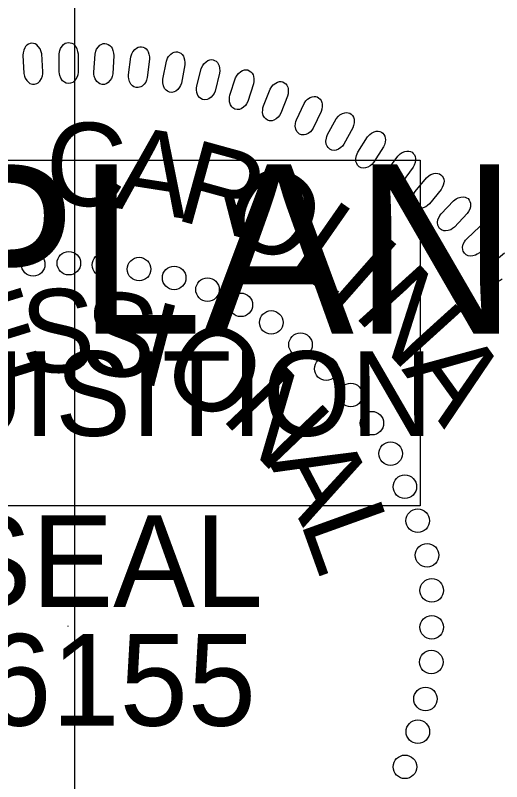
# Model space of a CAD drawing. Extents: x 497599 to 513368, y 404140 to 476034.
# Drawn here: x 507304.6 to 507337.7, y 439736.2 to 439788.3 of the extents above; entities that cross this region are included whole.
import ezdxf

# ---------------------------------------------------------------- set-up
doc = ezdxf.new("R2010")
doc.units = 0
for name, color, linetype in [('Sheet Layout Profile Border Port 2', 7, 'Continuous'), ('Sheet PE Seal Cell', 7, 'Continuous'), ('Sheet Sticker Incomplete CELL', 7, 'Continuous')]:
    doc.layers.add(name, color=color, linetype=linetype)

msp = doc.modelspace()

# ---------------------------------------------------------------- linework, layer by layer
at = {"layer": 'Sheet Layout Profile Border Port 2'}
msp.add_lwpolyline([(505908.678, 439836.144), (507308.678, 439836.144), (507308.678, 439336.144), (505908.678, 439336.144)], close=True, dxfattribs=at)
at = {"layer": 'Sheet PE Seal Cell'}
msp.add_line((507308.224, 439746.764), (507308.224, 439746.717), dxfattribs=at)
for points in [[(507306.517, 439784.44), (507306.441, 439785.665), (507306.39, 439785.881), (507306.329, 439786.017), (507306.206, 439786.18), (507306.103, 439786.283), (507305.986, 439786.356), (507305.879, 439786.389), (507305.765, 439786.401), (507305.655, 439786.374), (507305.538, 439786.337), (507305.436, 439786.271), (507305.338, 439786.165), (507305.284, 439786.082), (507305.226, 439785.928), (507305.177, 439785.745), (507305.165, 439785.585), (507305.236, 439784.33), (507305.269, 439784.162), (507305.323, 439784.026), (507305.422, 439783.872), (507305.543, 439783.74), (507305.644, 439783.666), (507305.805, 439783.616), (507305.956, 439783.605), (507306.102, 439783.655), (507306.204, 439783.711), (507306.324, 439783.819), (507306.433, 439783.995), (507306.489, 439784.179), (507306.511, 439784.31)], [(507307.633, 439784.449), (507307.633, 439785.676), (507307.671, 439785.895), (507307.723, 439786.035), (507307.835, 439786.204), (507307.933, 439786.314), (507308.045, 439786.394), (507308.149, 439786.434), (507308.262, 439786.454), (507308.373, 439786.434), (507308.493, 439786.404), (507308.597, 439786.344), (507308.702, 439786.244), (507308.762, 439786.164), (507308.829, 439786.014), (507308.889, 439785.835), (507308.912, 439785.675), (507308.918, 439784.419), (507308.896, 439784.249), (507308.851, 439784.11), (507308.761, 439783.95), (507308.649, 439783.81), (507308.552, 439783.731), (507308.395, 439783.671), (507308.246, 439783.651), (507308.096, 439783.691), (507307.992, 439783.741), (507307.864, 439783.84), (507307.745, 439784.011), (507307.677, 439784.19), (507307.648, 439784.32)], [(507309.992, 439784.423), (507310.069, 439785.647), (507310.12, 439785.864), (507310.181, 439786), (507310.304, 439786.162), (507310.408, 439786.265), (507310.525, 439786.338), (507310.632, 439786.371), (507310.745, 439786.384), (507310.856, 439786.356), (507310.973, 439786.319), (507311.074, 439786.253), (507311.172, 439786.147), (507311.226, 439786.063), (507311.285, 439785.91), (507311.333, 439785.727), (507311.345, 439785.567), (507311.273, 439784.312), (507311.24, 439784.144), (507311.186, 439784.007), (507311.087, 439783.854), (507310.966, 439783.722), (507310.864, 439783.648), (507310.704, 439783.598), (507310.553, 439783.587), (507310.406, 439783.637), (507310.305, 439783.694), (507310.185, 439783.801), (507310.076, 439783.978), (507310.02, 439784.161), (507309.999, 439784.293)], [(507312.354, 439784.248), (507312.509, 439785.464), (507312.573, 439785.678), (507312.643, 439785.809), (507312.775, 439785.963), (507312.886, 439786.06), (507313.007, 439786.125), (507313.115, 439786.152), (507313.229, 439786.157), (507313.338, 439786.123), (507313.452, 439786.079), (507313.549, 439786.006), (507313.64, 439785.894), (507313.69, 439785.808), (507313.738, 439785.65), (507313.774, 439785.465), (507313.776, 439785.304), (507313.626, 439784.056), (507313.582, 439783.891), (507313.521, 439783.758), (507313.411, 439783.611), (507313.283, 439783.487), (507313.177, 439783.42), (507313.013, 439783.38), (507312.862, 439783.379), (507312.719, 439783.437), (507312.621, 439783.5), (507312.507, 439783.615), (507312.41, 439783.798), (507312.366, 439783.985), (507312.353, 439784.117)], [(507314.694, 439783.961), (507314.924, 439785.166), (507315.002, 439785.374), (507315.079, 439785.501), (507315.222, 439785.647), (507315.337, 439785.736), (507315.462, 439785.794), (507315.573, 439785.813), (507315.687, 439785.812), (507315.793, 439785.772), (507315.905, 439785.72), (507315.996, 439785.641), (507316.081, 439785.523), (507316.124, 439785.434), (507316.162, 439785.274), (507316.188, 439785.087), (507316.18, 439784.926), (507315.951, 439783.69), (507315.897, 439783.528), (507315.827, 439783.399), (507315.709, 439783.259), (507315.572, 439783.143), (507315.462, 439783.083), (507315.297, 439783.054), (507315.146, 439783.062), (507315.007, 439783.129), (507314.913, 439783.198), (507314.807, 439783.32), (507314.722, 439783.509), (507314.689, 439783.698), (507314.684, 439783.831)], [(507316.999, 439783.487), (507317.304, 439784.675), (507317.395, 439784.878), (507317.481, 439785.001), (507317.631, 439785.137), (507317.753, 439785.219), (507317.881, 439785.268), (507317.992, 439785.281), (507318.106, 439785.273), (507318.21, 439785.226), (507318.318, 439785.166), (507318.405, 439785.083), (507318.481, 439784.96), (507318.519, 439784.868), (507318.547, 439784.706), (507318.56, 439784.517), (507318.543, 439784.357), (507318.237, 439783.138), (507318.172, 439782.98), (507318.094, 439782.856), (507317.968, 439782.724), (507317.824, 439782.616), (507317.711, 439782.563), (507317.544, 439782.544), (507317.394, 439782.562), (507317.259, 439782.638), (507317.17, 439782.712), (507317.072, 439782.84), (507316.998, 439783.035), (507316.978, 439783.225), (507316.981, 439783.358)], [(507319.249, 439782.865), (507319.628, 439784.032), (507319.732, 439784.229), (507319.825, 439784.345), (507319.984, 439784.472), (507320.11, 439784.546), (507320.241, 439784.588), (507320.353, 439784.593), (507320.466, 439784.577), (507320.567, 439784.524), (507320.671, 439784.458), (507320.753, 439784.369), (507320.821, 439784.242), (507320.853, 439784.147), (507320.871, 439783.984), (507320.872, 439783.795), (507320.844, 439783.636), (507320.462, 439782.439), (507320.389, 439782.285), (507320.303, 439782.166), (507320.168, 439782.041), (507320.018, 439781.944), (507319.901, 439781.898), (507319.733, 439781.89), (507319.585, 439781.917), (507319.455, 439782.001), (507319.371, 439782.081), (507319.281, 439782.215), (507319.22, 439782.413), (507319.211, 439782.605), (507319.223, 439782.737)], [(507321.532, 439782.13), (507321.984, 439783.271), (507322.1, 439783.461), (507322.2, 439783.572), (507322.367, 439783.688), (507322.498, 439783.754), (507322.631, 439783.787), (507322.743, 439783.785), (507322.855, 439783.763), (507322.951, 439783.703), (507323.052, 439783.631), (507323.127, 439783.537), (507323.187, 439783.405), (507323.214, 439783.309), (507323.221, 439783.146), (507323.211, 439782.956), (507323.173, 439782.8), (507322.717, 439781.629), (507322.633, 439781.48), (507322.54, 439781.366), (507322.398, 439781.251), (507322.242, 439781.162), (507322.123, 439781.124), (507321.954, 439781.127), (507321.808, 439781.163), (507321.684, 439781.255), (507321.605, 439781.34), (507321.523, 439781.48), (507321.475, 439781.681), (507321.478, 439781.873), (507321.499, 439782.005)], [(507323.774, 439781.196), (507324.296, 439782.306), (507324.423, 439782.489), (507324.53, 439782.593), (507324.704, 439782.698), (507324.838, 439782.756), (507324.974, 439782.78), (507325.086, 439782.772), (507325.196, 439782.742), (507325.288, 439782.676), (507325.384, 439782.599), (507325.453, 439782.5), (507325.505, 439782.365), (507325.526, 439782.267), (507325.523, 439782.103), (507325.5, 439781.915), (507325.453, 439781.761), (507324.924, 439780.621), (507324.832, 439780.478), (507324.731, 439780.37), (507324.582, 439780.264), (507324.421, 439780.186), (507324.299, 439780.155), (507324.131, 439780.167), (507323.988, 439780.214), (507323.87, 439780.313), (507323.797, 439780.402), (507323.724, 439780.547), (507323.688, 439780.751), (507323.703, 439780.943), (507323.732, 439781.072)], [(507325.898, 439780.181), (507326.489, 439781.256), (507326.627, 439781.43), (507326.74, 439781.527), (507326.92, 439781.621), (507327.058, 439781.671), (507327.195, 439781.687), (507327.306, 439781.671), (507327.414, 439781.635), (507327.502, 439781.563), (507327.593, 439781.479), (507327.656, 439781.376), (507327.699, 439781.239), (507327.713, 439781.14), (507327.701, 439780.976), (507327.666, 439780.79), (507327.609, 439780.64), (507327.009, 439779.535), (507326.908, 439779.397), (507326.802, 439779.296), (507326.646, 439779.2), (507326.48, 439779.132), (507326.357, 439779.108), (507326.19, 439779.132), (507326.05, 439779.186), (507325.938, 439779.293), (507325.87, 439779.388), (507325.807, 439779.537), (507325.784, 439779.742), (507325.812, 439779.932), (507325.848, 439780.061)], [(507327.956, 439778.996), (507328.613, 439780.031), (507328.762, 439780.197), (507328.881, 439780.286), (507329.067, 439780.37), (507329.208, 439780.41), (507329.345, 439780.417), (507329.455, 439780.395), (507329.561, 439780.351), (507329.644, 439780.275), (507329.729, 439780.185), (507329.786, 439780.079), (507329.82, 439779.938), (507329.828, 439779.839), (507329.805, 439779.676), (507329.759, 439779.493), (507329.692, 439779.346), (507329.025, 439778.281), (507328.915, 439778.151), (507328.802, 439778.057), (507328.641, 439777.97), (507328.472, 439777.912), (507328.347, 439777.896), (507328.182, 439777.93), (507328.045, 439777.994), (507327.941, 439778.107), (507327.879, 439778.206), (507327.825, 439778.358), (507327.815, 439778.565), (507327.854, 439778.753), (507327.899, 439778.879)], [(507329.955, 439777.723), (507330.677, 439778.715), (507330.836, 439778.871), (507330.961, 439778.953), (507331.151, 439779.024), (507331.294, 439779.056), (507331.431, 439779.055), (507331.54, 439779.025), (507331.642, 439778.975), (507331.721, 439778.893), (507331.8, 439778.799), (507331.849, 439778.689), (507331.876, 439778.546), (507331.877, 439778.447), (507331.844, 439778.286), (507331.786, 439778.106), (507331.711, 439777.963), (507330.978, 439776.943), (507330.86, 439776.819), (507330.741, 439776.732), (507330.575, 439776.656), (507330.402, 439776.609), (507330.276, 439776.602), (507330.115, 439776.645), (507329.982, 439776.718), (507329.884, 439776.837), (507329.829, 439776.939), (507329.785, 439777.095), (507329.788, 439777.302), (507329.839, 439777.487), (507329.891, 439777.61)], [(507331.85, 439776.306), (507332.632, 439777.251), (507332.801, 439777.397), (507332.93, 439777.471), (507333.125, 439777.53), (507333.269, 439777.553), (507333.407, 439777.543), (507333.512, 439777.507), (507333.612, 439777.45), (507333.685, 439777.364), (507333.758, 439777.264), (507333.801, 439777.152), (507333.818, 439777.008), (507333.813, 439776.908), (507333.769, 439776.75), (507333.701, 439776.574), (507333.617, 439776.436), (507332.821, 439775.464), (507332.696, 439775.347), (507332.572, 439775.268), (507332.402, 439775.203), (507332.226, 439775.166), (507332.1, 439775.167), (507331.941, 439775.221), (507331.813, 439775.301), (507331.723, 439775.427), (507331.675, 439775.532), (507331.641, 439775.69), (507331.657, 439775.897), (507331.719, 439776.079), (507331.779, 439776.197)], [(507333.621, 439774.792), (507334.462, 439775.687), (507334.639, 439775.821), (507334.773, 439775.887), (507334.971, 439775.934), (507335.117, 439775.947), (507335.253, 439775.929), (507335.357, 439775.886), (507335.452, 439775.824), (507335.52, 439775.732), (507335.586, 439775.629), (507335.622, 439775.514), (507335.63, 439775.369), (507335.619, 439775.269), (507335.565, 439775.115), (507335.486, 439774.943), (507335.394, 439774.812), (507334.538, 439773.891), (507334.406, 439773.783), (507334.277, 439773.712), (507334.103, 439773.657), (507333.926, 439773.631), (507333.8, 439773.64), (507333.644, 439773.704), (507333.522, 439773.792), (507333.441, 439773.923), (507333.398, 439774.031), (507333.374, 439774.191), (507333.403, 439774.396), (507333.477, 439774.573), (507333.544, 439774.688)], [(507335.366, 439773.099), (507336.26, 439773.939), (507336.446, 439774.061), (507336.584, 439774.119), (507336.784, 439774.153), (507336.93, 439774.157), (507337.065, 439774.13), (507337.166, 439774.081), (507337.258, 439774.013), (507337.319, 439773.917), (507337.38, 439773.81), (507337.408, 439773.693), (507337.407, 439773.548), (507337.389, 439773.45), (507337.326, 439773.299), (507337.236, 439773.132), (507337.135, 439773.006), (507336.224, 439772.141), (507336.085, 439772.042), (507335.952, 439771.979), (507335.775, 439771.935), (507335.596, 439771.921), (507335.471, 439771.937), (507335.32, 439772.011), (507335.203, 439772.106), (507335.13, 439772.242), (507335.095, 439772.353), (507335.081, 439772.514), (507335.123, 439772.717), (507335.208, 439772.889), (507335.282, 439773)]]:
    msp.add_lwpolyline(points, close=True, dxfattribs=at)
msp.add_lwpolyline([(507337.774, 439770.343), (507337.629, 439770.252), (507337.493, 439770.198), (507337.313, 439770.166), (507337.134, 439770.163), (507337.01, 439770.187), (507336.864, 439770.269), (507336.754, 439770.372), (507336.689, 439770.513), (507336.661, 439770.625), (507336.657, 439770.787), (507336.711, 439770.987), (507336.807, 439771.153), (507336.888, 439771.259), (507336.978, 439771.353), (507337.923, 439772.135)], dxfattribs=at)
for centre in [(507305.861, 439771.353), (507308.29, 439771.432), (507310.678, 439771.312), (507313.067, 439771.032), (507315.456, 439770.434), (507317.725, 439769.637), (507319.994, 439768.6), (507322.064, 439767.404), (507324.054, 439765.89), (507325.805, 439764.256), (507327.477, 439762.463), (507328.909, 439760.55), (507330.183, 439758.478), (507331.155, 439756.229), (507332.03, 439753.918), (507332.666, 439751.567), (507332.984, 439749.177), (507332.983, 439746.667), (507332.953, 439744.304), (507332.554, 439741.794), (507332.036, 439739.563), (507331.159, 439737.173)]:
    msp.add_circle(centre, 0.801, dxfattribs=at)
at = {"layer": 'Sheet Sticker Incomplete CELL'}
msp.add_lwpolyline([(507185.195, 439754.938), (507185.195, 439778.438), (507332.195, 439778.438), (507332.195, 439754.938)], close=True, dxfattribs=at)

# ---------------------------------------------------------------- texts
at = {"layer": 'Sheet PE Seal Cell'}
for s, height, rotation, p in [('C', 5.669, 357.5877, (507306.608, 439775.444)), ('A', 5.669, 351.0983, (507311.183, 439775.235)), ('R', 5.669, 344.609, (507315.389, 439774.441)), ('O', 5.669, 331.6302, (507318.344, 439773.787)), ('L', 5.669, 325.1409, (507323.077, 439771.256)), ('I', 5.669, 318.6515, (507325.77, 439769.403)), ('N', 5.669, 312.1622, (507327.575, 439767.983)), ('E', 5.669, 17.1686, (507302.299, 439762.991)), ('S', 5.669, 1.289, (507305.066, 439763.951)), ('S', 5.669, 353.3492, (507308.927, 439764.052)), ('I', 5.669, 345.4094, (507312.727, 439763.42)), ('O', 5.669, 329.5298, (507314.231, 439763.249)), ('A', 5.669, 305.6728, (507330.895, 439764.202)), ('N', 5.669, 313.6502, (507318.543, 439760.944)), ('A', 5.669, 297.7707, (507321.88, 439757.864)), ('L', 5.669, 289.8309, (507324.003, 439753.869)), ('SEAL', 6.2363, 359.9814, (507300.182, 439748.057)), ('46155', 6.2363, 359.9814, (507297.834, 439739.978))]:
    msp.add_text(s, height=height, rotation=rotation, dxfattribs=at).set_placement(p)
at = {"layer": 'Sheet Sticker Incomplete CELL'}
for s, height, p in [('INCOMPLETE PLANS', 11.52, (507194.145, 439766.638)), ('DO NOT USE FOR R/W ACQUISITION', 5.76, (507197.395, 439759.688))]:
    msp.add_text(s, height=height, dxfattribs=at).set_placement(p)

doc.saveas('drawing.dxf')
